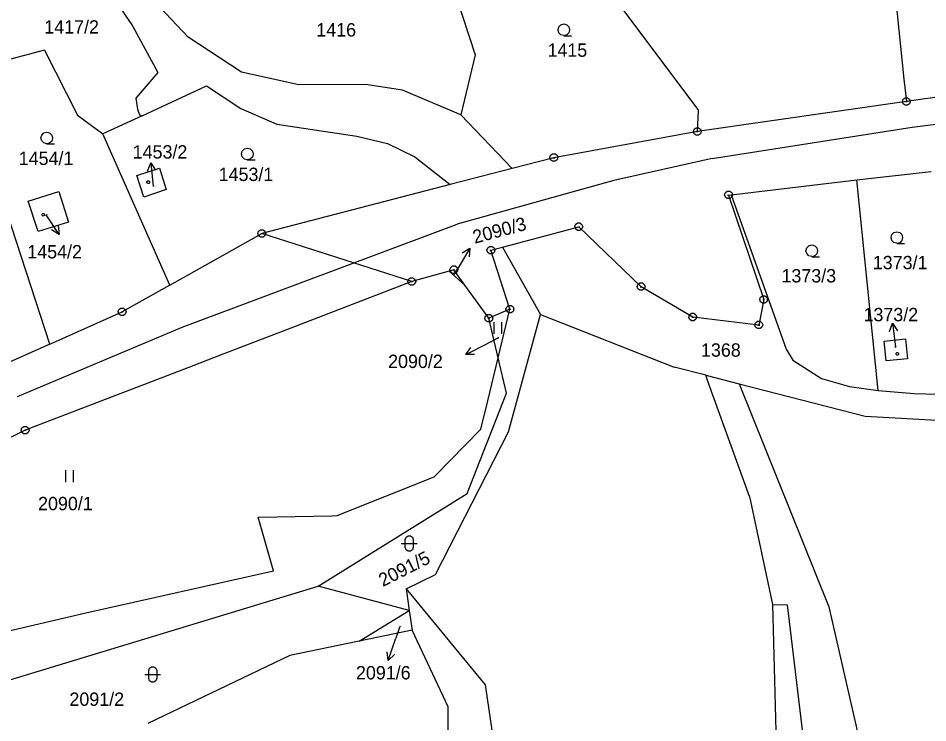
# Model space of a CAD drawing. Extents: x -806774 to -803680, y -1151731 to -1150053.
# Drawn here: x -804923.9 to -804808.2, y -1150604.7 to -1150515.1 of the extents above; entities that cross this region are included whole.
import ezdxf

# ---------------------------------------------------------------- set-up
doc = ezdxf.new("R2010")
doc.units = 0
for name, color, linetype in [('1', 7, 'Continuous'), ('12', 7, 'Continuous'), ('2', 7, 'Continuous'), ('3', 7, 'Continuous'), ('5', 7, 'Continuous'), ('6', 7, 'Continuous'), ('7', 7, 'Continuous'), ('8', 7, 'Continuous')]:
    doc.layers.add(name, color=color, linetype=linetype)

msp = doc.modelspace()

# ---------------------------------------------------------------- linework, layer by layer
at = {"layer": '1'}
for p, q in [((-804813.68, -1150499.24), (-804811.2, -1150522.83)), ((-804854.06, -1150504.46), (-804837.36, -1150526.82)), ((-804870.5, -1150505.04), (-804865.77, -1150519.74)), ((-804911.38, -1150513.07), (-804909.35, -1150516.02)), ((-804902.3, -1150517.47), (-804906.56, -1150512.95)), ((-804909.35, -1150516.02), (-804906.16, -1150521.98)), ((-804895.5, -1150521.92), (-804902.3, -1150517.47)), ((-804920.55, -1150519.13), (-804925.98, -1150520.59)), ((-804920.55, -1150519.13), (-804916.36, -1150527.41)), ((-804865.77, -1150519.74), (-804867.58, -1150527.37)), ((-804888.2, -1150523.55), (-804895.5, -1150521.92)), ((-804919.88, -1150556.55), (-804931.17, -1150521.99)), ((-804906.16, -1150521.98), (-804908.94, -1150525.24)), ((-804811.2, -1150522.83), (-804810.9, -1150525.68)), ((-804908.15, -1150527.49), (-804899.94, -1150523.69)), ((-804899.94, -1150523.69), (-804895.6, -1150526.55)), ((-804879.72, -1150523.51), (-804888.2, -1150523.55)), ((-804874.99, -1150524.22), (-804879.72, -1150523.51)), ((-804867.58, -1150527.37), (-804874.99, -1150524.22)), ((-804795.05, -1150523.42), (-804810.9, -1150525.68)), ((-804908.94, -1150525.24), (-804908.74, -1150526.63)), ((-804895.6, -1150526.55), (-804891, -1150528.55)), ((-804810.9, -1150525.68), (-804837.49, -1150529.49)), ((-804916.36, -1150527.41), (-804913.13, -1150529.8)), ((-804908.15, -1150527.49), (-804913.13, -1150529.8)), ((-804908.74, -1150526.63), (-804908.49, -1150527.35)), ((-804908.49, -1150527.35), (-804908.26, -1150527.45)), ((-804908.26, -1150527.45), (-804908.15, -1150527.49)), ((-804867.58, -1150527.37), (-804861.97, -1150533.23)), ((-804837.49, -1150529.49), (-804837.36, -1150526.82)), ((-804891, -1150528.55), (-804880.82, -1150530.09)), ((-804904.62, -1150549.05), (-804913.13, -1150529.8)), ((-804837.49, -1150529.49), (-804855.75, -1150532.82)), ((-804880.82, -1150530.09), (-804876.91, -1150531.02)), ((-804876.91, -1150531.02), (-804873.43, -1150532.72)), ((-804873.43, -1150532.72), (-804870.09, -1150535.34)), ((-804861.97, -1150533.23), (-804861.04, -1150534.2)), ((-804855.75, -1150532.82), (-804861.04, -1150534.2)), ((-804908.82, -1150535.1), (-804905.94, -1150534.15)), ((-804905.94, -1150534.15), (-804905.08, -1150536.89)), ((-804861.04, -1150534.2), (-804868.93, -1150536.25)), ((-804817.19, -1150535.66), (-804807.75, -1150534.56)), ((-804907.92, -1150537.83), (-804908.82, -1150535.1)), ((-804870.09, -1150535.34), (-804868.93, -1150536.25)), ((-804833.21, -1150537.53), (-804817.19, -1150535.66)), ((-804814.48, -1150562.46), (-804817.19, -1150535.66)), ((-804905.08, -1150536.89), (-804907.92, -1150537.83)), ((-804868.93, -1150536.25), (-804892.91, -1150542.49)), ((-804922.62, -1150538.35), (-804918.73, -1150537.14)), ((-804918.73, -1150537.14), (-804917.51, -1150541.02)), ((-804833.52, -1150537.57), (-804833.21, -1150537.53)), ((-804833.52, -1150537.57), (-804829.05, -1150550.88)), ((-804833.21, -1150537.53), (-804826.21, -1150557.2)), ((-804921.35, -1150542.23), (-804922.62, -1150538.35)), ((-804917.51, -1150541.02), (-804921.35, -1150542.23)), ((-804862.3, -1150544.21), (-804852.58, -1150541.61)), ((-804844.64, -1150549.24), (-804852.58, -1150541.61)), ((-804904.62, -1150549.05), (-804892.91, -1150542.49)), ((-804873.83, -1150548.59), (-804892.91, -1150542.49)), ((-804863.76, -1150544.6), (-804862.3, -1150544.21)), ((-804861.34, -1150552.12), (-804863.76, -1150544.6)), ((-804862.3, -1150544.21), (-804857.45, -1150552.76)), ((-804869.09, -1150547.25), (-804873.83, -1150548.59)), ((-804868.47, -1150547.08), (-804869.09, -1150547.25)), ((-804867.07, -1150549.03), (-804869.09, -1150547.25)), ((-804867.07, -1150549.03), (-804868.47, -1150547.08)), ((-804904.62, -1150549.05), (-804910.68, -1150552.45)), ((-804873.83, -1150548.59), (-804889.79, -1150554.73)), ((-804864.02, -1150553.26), (-804867.07, -1150549.03)), ((-804838.07, -1150553.11), (-804844.64, -1150549.24)), ((-804829.05, -1150550.88), (-804829.67, -1150554.12)), ((-804919.88, -1150556.55), (-804910.68, -1150552.45)), ((-804861.34, -1150552.12), (-804864.02, -1150553.26)), ((-804862.83, -1150558.29), (-804861.34, -1150552.12)), ((-804861.53, -1150567.7), (-804857.45, -1150552.76)), ((-804857.45, -1150552.76), (-804840.45, -1150559.48)), ((-804829.67, -1150554.12), (-804838.07, -1150553.11)), ((-804862.83, -1150558.29), (-804864.02, -1150553.26)), ((-804889.79, -1150554.73), (-804898.28, -1150557.99)), ((-804919.88, -1150556.55), (-804930.31, -1150561.21)), ((-804813.72, -1150556.16), (-804811.01, -1150555.88)), ((-804813.46, -1150558.69), (-804813.72, -1150556.16)), ((-804811.01, -1150555.88), (-804810.75, -1150558.41)), ((-804826.21, -1150557.2), (-804825.34, -1150558.58)), ((-804898.28, -1150557.99), (-804902.34, -1150559.55)), ((-804864.15, -1150563.75), (-804862.83, -1150558.29)), ((-804861.77, -1150562.79), (-804862.83, -1150558.29)), ((-804825.34, -1150558.58), (-804821.71, -1150560.94)), ((-804810.75, -1150558.41), (-804813.46, -1150558.69)), ((-804902.34, -1150559.55), (-804906.85, -1150561.29)), ((-804836.43, -1150560.51), (-804840.45, -1150559.48)), ((-804906.85, -1150561.29), (-804923.02, -1150567.51)), ((-804836.07, -1150561.51), (-804836.43, -1150560.51)), ((-804836.43, -1150560.51), (-804832.17, -1150561.6)), ((-804821.71, -1150560.94), (-804818.13, -1150561.93)), ((-804830.85, -1150575.93), (-804836.07, -1150561.51)), ((-804832.17, -1150561.6), (-804820.76, -1150589.98)), ((-804832.17, -1150561.6), (-804816.13, -1150565.71)), ((-804818.13, -1150561.93), (-804814.48, -1150562.46)), ((-804866.78, -1150575.55), (-804861.77, -1150562.79)), ((-804814.48, -1150562.46), (-804809.9, -1150562.82)), ((-804809.9, -1150562.82), (-804805.12, -1150562.96)), ((-804865.03, -1150567.37), (-804864.15, -1150563.75)), ((-804816.13, -1150565.71), (-804791.75, -1150567.1)), ((-804923.02, -1150567.51), (-804951.89, -1150581.61)), ((-804870.98, -1150573.44), (-804865.03, -1150567.37)), ((-804870.83, -1150585.85), (-804861.53, -1150567.7)), ((-804883.31, -1150578.38), (-804870.98, -1150573.44)), ((-804885.76, -1150587.34), (-804866.78, -1150575.55)), ((-804830.85, -1150575.93), (-804827.95, -1150589.7)), ((-804893.36, -1150578.56), (-804891.02, -1150578.52)), ((-804891.43, -1150585.39), (-804893.36, -1150578.56)), ((-804891.02, -1150578.52), (-804883.96, -1150578.39)), ((-804883.96, -1150578.39), (-804883.31, -1150578.38)), ((-804915.29, -1150590.76), (-804891.43, -1150585.39)), ((-804874.55, -1150587.71), (-804870.83, -1150585.85)), ((-804942.25, -1150604.51), (-804885.76, -1150587.34)), ((-804874.15, -1150590.46), (-804885.76, -1150587.34)), ((-804874.55, -1150587.71), (-804864.48, -1150599.92)), ((-804874.55, -1150587.71), (-804874.15, -1150590.46)), ((-804827.95, -1150589.7), (-804827.34, -1150611.64)), ((-804827.95, -1150589.7), (-804826.08, -1150589.72)), ((-804826.08, -1150589.72), (-804823.4, -1150611.86)), ((-804820.76, -1150589.98), (-804815.75, -1150611.81)), ((-804941.23, -1150596.81), (-804915.29, -1150590.76)), ((-804880.53, -1150594.36), (-804874.15, -1150590.46)), ((-804874.15, -1150590.46), (-804873.79, -1150592.97)), ((-804873.79, -1150592.97), (-804880.53, -1150594.36)), ((-804869.21, -1150602.7), (-804873.79, -1150592.97)), ((-804880.53, -1150594.36), (-804889.34, -1150596.17)), ((-804889.34, -1150596.17), (-804907.43, -1150604.85)), ((-804864.48, -1150599.92), (-804859.64, -1150632.81)), ((-804869.15, -1150627.88), (-804869.21, -1150602.7))]:
    msp.add_line(p, q, dxfattribs=at)
at = {"layer": '12'}
for p, q in [((-804908.82, -1150535.1), (-804905.94, -1150534.15)), ((-804905.94, -1150534.15), (-804905.08, -1150536.89)), ((-804907.92, -1150537.83), (-804908.82, -1150535.1)), ((-804905.08, -1150536.89), (-804907.92, -1150537.83)), ((-804922.62, -1150538.35), (-804918.73, -1150537.14)), ((-804918.73, -1150537.14), (-804917.51, -1150541.02)), ((-804921.35, -1150542.23), (-804922.62, -1150538.35)), ((-804917.51, -1150541.02), (-804921.35, -1150542.23)), ((-804813.72, -1150556.16), (-804811.01, -1150555.88)), ((-804813.46, -1150558.69), (-804813.72, -1150556.16)), ((-804811.01, -1150555.88), (-804810.75, -1150558.41)), ((-804810.75, -1150558.41), (-804813.46, -1150558.69))]:
    msp.add_line(p, q, dxfattribs=at)
at = {"layer": '3'}
for p, q in [((-804863.39, -1150553.75), (-804863.39, -1150555.25)), ((-804862.39, -1150555.25), (-804862.39, -1150553.75)), ((-804917.88, -1150572.6), (-804917.88, -1150574.1)), ((-804916.88, -1150574.1), (-804916.88, -1150572.6))]:
    msp.add_line(p, q, dxfattribs=at)
for points in [[(-804854.47, -1150517.28), (-804854.85, -1150517.18), (-804855.12, -1150516.91), (-804855.22, -1150516.54), (-804855.12, -1150516.17), (-804854.85, -1150515.9), (-804854.48, -1150515.8), (-804854.11, -1150515.9), (-804853.84, -1150516.17), (-804853.74, -1150516.55), (-804853.84, -1150516.93), (-804854.11, -1150517.2), (-804854.49, -1150517.3), (-804853.49, -1150517.3)], [(-804920.27, -1150531.05), (-804920.65, -1150530.95), (-804920.92, -1150530.68), (-804921.02, -1150530.31), (-804920.92, -1150529.94), (-804920.65, -1150529.67), (-804920.28, -1150529.57), (-804919.91, -1150529.67), (-804919.64, -1150529.94), (-804919.54, -1150530.32), (-804919.64, -1150530.7), (-804919.91, -1150530.97), (-804920.29, -1150531.07), (-804919.29, -1150531.07)], [(-804894.74, -1150533.09), (-804895.12, -1150532.99), (-804895.39, -1150532.72), (-804895.49, -1150532.35), (-804895.39, -1150531.98), (-804895.12, -1150531.71), (-804894.75, -1150531.61), (-804894.38, -1150531.71), (-804894.11, -1150531.98), (-804894.01, -1150532.36), (-804894.11, -1150532.74), (-804894.38, -1150533.01), (-804894.76, -1150533.11), (-804893.76, -1150533.11)], [(-804812.1, -1150543.72), (-804812.48, -1150543.62), (-804812.75, -1150543.35), (-804812.85, -1150542.98), (-804812.75, -1150542.61), (-804812.48, -1150542.34), (-804812.11, -1150542.24), (-804811.74, -1150542.34), (-804811.47, -1150542.61), (-804811.37, -1150542.99), (-804811.47, -1150543.37), (-804811.74, -1150543.64), (-804812.12, -1150543.74), (-804811.12, -1150543.74)], [(-804822.92, -1150545.4), (-804823.3, -1150545.3), (-804823.57, -1150545.03), (-804823.67, -1150544.66), (-804823.57, -1150544.29), (-804823.3, -1150544.02), (-804822.93, -1150543.92), (-804822.56, -1150544.02), (-804822.29, -1150544.29), (-804822.19, -1150544.67), (-804822.29, -1150545.05), (-804822.56, -1150545.32), (-804822.94, -1150545.42), (-804821.94, -1150545.42)], [(-804875.16, -1150581.92), (-804873.89, -1150581.92), (-804873.16, -1150581.92)], [(-804907.79, -1150598.6), (-804906.52, -1150598.6), (-804905.79, -1150598.6)]]:
    msp.add_lwpolyline(points, dxfattribs=at)
for points in [[(-804874.66, -1150581.42), (-804874.56, -1150581.13), (-804874.31, -1150580.95), (-804874, -1150580.95), (-804873.75, -1150581.13), (-804873.65, -1150581.42), (-804873.65, -1150582.42), (-804873.75, -1150582.71), (-804874, -1150582.89), (-804874.31, -1150582.89), (-804874.56, -1150582.71), (-804874.66, -1150582.42)], [(-804907.29, -1150598.1), (-804907.19, -1150597.81), (-804906.94, -1150597.63), (-804906.63, -1150597.63), (-804906.38, -1150597.81), (-804906.28, -1150598.1), (-804906.28, -1150599.1), (-804906.38, -1150599.39), (-804906.63, -1150599.57), (-804906.94, -1150599.57), (-804907.19, -1150599.39), (-804907.29, -1150599.1)]]:
    msp.add_lwpolyline(points, close=True, dxfattribs=at)
at = {"layer": '5'}
for points in [[(-804907.37, -1150535.76), (-804907.27, -1150535.78), (-804907.22, -1150535.87), (-804907.2, -1150535.93), (-804907.22, -1150536.02), (-804907.3, -1150536.09), (-804907.37, -1150536.1), (-804907.46, -1150536.07), (-804907.52, -1150536.01), (-804907.54, -1150535.93), (-804907.52, -1150535.84), (-804907.44, -1150535.77)], [(-804920.72, -1150539.91), (-804920.62, -1150539.93), (-804920.57, -1150540.02), (-804920.55, -1150540.08), (-804920.57, -1150540.17), (-804920.65, -1150540.24), (-804920.72, -1150540.25), (-804920.81, -1150540.22), (-804920.87, -1150540.16), (-804920.89, -1150540.08), (-804920.87, -1150539.99), (-804920.79, -1150539.92)], [(-804812.06, -1150557.62), (-804811.96, -1150557.64), (-804811.91, -1150557.73), (-804811.89, -1150557.79), (-804811.91, -1150557.88), (-804811.99, -1150557.95), (-804812.06, -1150557.96), (-804812.15, -1150557.93), (-804812.21, -1150557.87), (-804812.23, -1150557.79), (-804812.21, -1150557.7), (-804812.13, -1150557.63)]]:
    msp.add_lwpolyline(points, close=True, dxfattribs=at)
at = {"layer": '6'}
for p, q in [((-804810.18, -1150528.95), (-804786.1, -1150525.82)), ((-804835.59, -1150532.92), (-804810.18, -1150528.95)), ((-804835.59, -1150532.92), (-804848.13, -1150535.71)), ((-804848.13, -1150535.71), (-804868.05, -1150541.29)), ((-804903.06, -1150554.4), (-804868.05, -1150541.29)), ((-804923.99, -1150563.23), (-804903.06, -1150554.4))]:
    msp.add_line(p, q, dxfattribs=at)
at = {"layer": '7'}
for p, q in [((-804907.05, -1150533.49), (-804906.74, -1150536.47)), ((-804918.7, -1150542.58), (-804920.37, -1150540.08)), ((-804866.46, -1150544.33), (-804867.98, -1150546.92)), ((-804868.43, -1150547.68), (-804867.98, -1150546.92)), ((-804812.65, -1150553.9), (-804812.3, -1150556.88)), ((-804866.96, -1150557.89), (-804864.3, -1150556.51)), ((-804862.8, -1150555.73), (-804864.3, -1150556.51)), ((-804812.29, -1150556.99), (-804812.3, -1150556.88)), ((-804875.37, -1150592.47), (-804875.87, -1150593.97)), ((-804876.82, -1150596.82), (-804875.87, -1150593.97))]:
    msp.add_line(p, q, dxfattribs=at)
for points in [[(-804907.45, -1150534.53), (-804907.05, -1150533.49), (-804906.45, -1150534.43)], [(-804918.84, -1150541.47), (-804918.7, -1150542.58), (-804919.68, -1150542.02)], [(-804867.4, -1150544.94), (-804866.46, -1150544.33), (-804866.54, -1150545.45)], [(-804813.03, -1150554.95), (-804812.65, -1150553.9), (-804812.03, -1150554.84)], [(-804865.84, -1150557.88), (-804866.96, -1150557.89), (-804866.31, -1150556.99)], [(-804876.03, -1150596.03), (-804876.82, -1150596.82), (-804876.98, -1150595.71)]]:
    msp.add_lwpolyline(points, dxfattribs=at)
at = {"layer": '8'}
for p, q in [((-804811.02, -1150525.68), (-804810.78, -1150525.68)), ((-804837.61, -1150529.49), (-804837.37, -1150529.49)), ((-804855.87, -1150532.82), (-804855.63, -1150532.82)), ((-804833.64, -1150537.57), (-804833.4, -1150537.57)), ((-804852.7, -1150541.61), (-804852.46, -1150541.61)), ((-804893.03, -1150542.49), (-804892.79, -1150542.49)), ((-804863.88, -1150544.6), (-804863.64, -1150544.6)), ((-804868.59, -1150547.08), (-804868.35, -1150547.08)), ((-804873.95, -1150548.59), (-804873.71, -1150548.59)), ((-804844.76, -1150549.24), (-804844.52, -1150549.24)), ((-804829.17, -1150550.88), (-804828.93, -1150550.88)), ((-804910.8, -1150552.45), (-804910.56, -1150552.45)), ((-804861.46, -1150552.12), (-804861.22, -1150552.12)), ((-804838.19, -1150553.11), (-804837.95, -1150553.11)), ((-804864.14, -1150553.26), (-804863.9, -1150553.26)), ((-804829.79, -1150554.12), (-804829.55, -1150554.12)), ((-804923.14, -1150567.51), (-804922.9, -1150567.51))]:
    msp.add_line(p, q, dxfattribs=at)
for points in [[(-804810.75, -1150525.2), (-804810.5, -1150525.38), (-804810.4, -1150525.67), (-804810.5, -1150525.96), (-804810.75, -1150526.14), (-804811.06, -1150526.14), (-804811.31, -1150525.96), (-804811.41, -1150525.67), (-804811.31, -1150525.38), (-804811.06, -1150525.2)], [(-804837.34, -1150529.01), (-804837.09, -1150529.19), (-804836.99, -1150529.48), (-804837.09, -1150529.77), (-804837.34, -1150529.95), (-804837.65, -1150529.95), (-804837.9, -1150529.77), (-804838, -1150529.48), (-804837.9, -1150529.19), (-804837.65, -1150529.01)], [(-804855.6, -1150532.34), (-804855.35, -1150532.52), (-804855.25, -1150532.81), (-804855.35, -1150533.1), (-804855.6, -1150533.28), (-804855.91, -1150533.28), (-804856.16, -1150533.1), (-804856.26, -1150532.81), (-804856.16, -1150532.52), (-804855.91, -1150532.34)], [(-804833.37, -1150537.09), (-804833.12, -1150537.27), (-804833.02, -1150537.56), (-804833.12, -1150537.85), (-804833.37, -1150538.03), (-804833.68, -1150538.03), (-804833.93, -1150537.85), (-804834.03, -1150537.56), (-804833.93, -1150537.27), (-804833.68, -1150537.09)], [(-804852.43, -1150541.13), (-804852.18, -1150541.31), (-804852.08, -1150541.6), (-804852.18, -1150541.89), (-804852.43, -1150542.07), (-804852.74, -1150542.07), (-804852.99, -1150541.89), (-804853.09, -1150541.6), (-804852.99, -1150541.31), (-804852.74, -1150541.13)], [(-804892.76, -1150542.01), (-804892.51, -1150542.19), (-804892.41, -1150542.48), (-804892.51, -1150542.77), (-804892.76, -1150542.95), (-804893.07, -1150542.95), (-804893.32, -1150542.77), (-804893.42, -1150542.48), (-804893.32, -1150542.19), (-804893.07, -1150542.01)], [(-804863.61, -1150544.12), (-804863.36, -1150544.3), (-804863.26, -1150544.59), (-804863.36, -1150544.88), (-804863.61, -1150545.06), (-804863.92, -1150545.06), (-804864.17, -1150544.88), (-804864.27, -1150544.59), (-804864.17, -1150544.3), (-804863.92, -1150544.12)], [(-804868.32, -1150546.6), (-804868.07, -1150546.78), (-804867.97, -1150547.07), (-804868.07, -1150547.36), (-804868.32, -1150547.54), (-804868.63, -1150547.54), (-804868.88, -1150547.36), (-804868.98, -1150547.07), (-804868.88, -1150546.78), (-804868.63, -1150546.6)], [(-804873.68, -1150548.11), (-804873.43, -1150548.29), (-804873.33, -1150548.58), (-804873.43, -1150548.87), (-804873.68, -1150549.05), (-804873.99, -1150549.05), (-804874.24, -1150548.87), (-804874.34, -1150548.58), (-804874.24, -1150548.29), (-804873.99, -1150548.11)], [(-804844.49, -1150548.76), (-804844.24, -1150548.94), (-804844.14, -1150549.23), (-804844.24, -1150549.52), (-804844.49, -1150549.7), (-804844.8, -1150549.7), (-804845.05, -1150549.52), (-804845.15, -1150549.23), (-804845.05, -1150548.94), (-804844.8, -1150548.76)], [(-804828.9, -1150550.4), (-804828.65, -1150550.58), (-804828.55, -1150550.87), (-804828.65, -1150551.16), (-804828.9, -1150551.34), (-804829.21, -1150551.34), (-804829.46, -1150551.16), (-804829.56, -1150550.87), (-804829.46, -1150550.58), (-804829.21, -1150550.4)], [(-804910.53, -1150551.97), (-804910.28, -1150552.15), (-804910.18, -1150552.44), (-804910.28, -1150552.73), (-804910.53, -1150552.91), (-804910.84, -1150552.91), (-804911.09, -1150552.73), (-804911.19, -1150552.44), (-804911.09, -1150552.15), (-804910.84, -1150551.97)], [(-804861.19, -1150551.64), (-804860.94, -1150551.82), (-804860.84, -1150552.11), (-804860.94, -1150552.4), (-804861.19, -1150552.58), (-804861.5, -1150552.58), (-804861.75, -1150552.4), (-804861.85, -1150552.11), (-804861.75, -1150551.82), (-804861.5, -1150551.64)], [(-804863.87, -1150552.78), (-804863.62, -1150552.96), (-804863.52, -1150553.25), (-804863.62, -1150553.54), (-804863.87, -1150553.72), (-804864.18, -1150553.72), (-804864.43, -1150553.54), (-804864.53, -1150553.25), (-804864.43, -1150552.96), (-804864.18, -1150552.78)], [(-804837.92, -1150552.63), (-804837.67, -1150552.81), (-804837.57, -1150553.1), (-804837.67, -1150553.39), (-804837.92, -1150553.57), (-804838.23, -1150553.57), (-804838.48, -1150553.39), (-804838.58, -1150553.1), (-804838.48, -1150552.81), (-804838.23, -1150552.63)], [(-804829.52, -1150553.64), (-804829.27, -1150553.82), (-804829.17, -1150554.11), (-804829.27, -1150554.4), (-804829.52, -1150554.58), (-804829.83, -1150554.58), (-804830.08, -1150554.4), (-804830.18, -1150554.11), (-804830.08, -1150553.82), (-804829.83, -1150553.64)], [(-804922.87, -1150567.03), (-804922.62, -1150567.21), (-804922.52, -1150567.5), (-804922.62, -1150567.79), (-804922.87, -1150567.97), (-804923.18, -1150567.97), (-804923.43, -1150567.79), (-804923.53, -1150567.5), (-804923.43, -1150567.21), (-804923.18, -1150567.03)]]:
    msp.add_lwpolyline(points, close=True, dxfattribs=at)

# ---------------------------------------------------------------- texts
at = {"layer": '2'}
for s, height, p in [('1417/2', 1.7, (-804920.59, -1150517.03)), ('1416', 1.7, (-804885.98, -1150517.4)), ('1415', 1.7, (-804856.56, -1150519.98)), ('1454/1', 1.7, (-804923.84, -1150533.75)), ('1453/1', 1.7, (-804898.4, -1150535.79)), ('1453/2', 0.1, (-804906.72, -1150536.47)), ('1454/2', 0.1, (-804920.35, -1150540.08)), ('1373/1', 1.7, (-804815.17, -1150547.02)), ('1373/3', 1.7, (-804826.79, -1150548.7)), ('2090/3', 0.1, (-804868.69, -1150547.68)), ('2090/2', 0.1, (-804863.05, -1150555.73)), ('1368', 1.7, (-804837.03, -1150558.15)), ('1373/2', 0.1, (-804812.52, -1150556.99)), ('2090/1', 1.7, (-804921.38, -1150577.69)), ('2091/6', 0.1, (-804875.36, -1150592.47)), ('2091/2', 1.7, (-804917.39, -1150602.59))]:
    msp.add_text(s, height=height, dxfattribs=at).set_placement(p)
msp.add_text('2091/5', height=1.7, rotation=26.9863, dxfattribs=at).set_placement((-804877.51, -1150587.48))
at = {"layer": '7'}
for s, p in [('1453/2', (-804909.34, -1150532.93)), ('1454/2', (-804922.75, -1150545.64)), ('1373/2', (-804816.35, -1150553.64)), ('2090/2', (-804876.84, -1150559.59)), ('2091/6', (-804880.93, -1150599.22))]:
    msp.add_text(s, height=1.7, dxfattribs=at).set_placement(p)
msp.add_text('2090/3', height=1.7, rotation=15.0688, dxfattribs=at).set_placement((-804865.82, -1150543.78))

doc.saveas('drawing.dxf')
